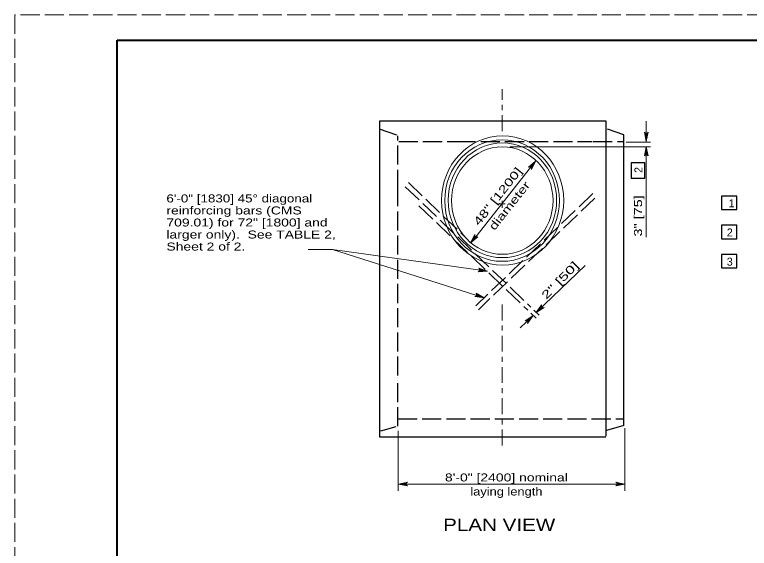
# Model space of a CAD drawing. Extents: x 1170.6 to 1204.6, y 975 to 1019.
# Drawn here: x 1170.59 to 1184.91, y 1008.62 to 1019.03 of the extents above; entities that cross this region are included whole.
import ezdxf
from ezdxf.enums import TextEntityAlignment as Align

# ---------------------------------------------------------------- set-up
doc = ezdxf.new("R2010")
doc.units = 0
doc.header["$LTSCALE"] = 0.062
doc.linetypes.add('DOT_DASHED', pattern=[7.7, 5, -1.2, 0.3, -1.2])
doc.linetypes.add('LONG_DASHED', pattern=[7.5, 6, -1.5])
doc.layers.add('1', color=7, linetype='Continuous', lineweight=13)

msp = doc.modelspace()

# ---------------------------------------------------------------- linework, layer by layer
at = {"layer": '1', "lineweight": 25}
for p, q in [((1172.59275, 1018.52625), (1204.09275, 1018.52625)), ((1177.70983, 1011.85525), (1177.70983, 1016.95867)), ((1177.70983, 1016.95867), (1178.63542, 1016.95867)), ((1178.61925, 1016.95867), (1181.86783, 1016.95867)), ((1182.46725, 1016.683), (1182.1455, 1016.79658)), ((1182.46725, 1011.89892), (1182.46725, 1016.683)), ((1177.70983, 1011.22067), (1177.70983, 1011.94267)), ((1182.11483, 1011.94267), (1182.11483, 1010.805)), ((1182.46725, 1011.01492), (1182.46725, 1011.94267)), ((1182.46725, 1011.01492), (1182.13008, 1010.9175)), ((1182.11483, 1010.78767), (1178.61925, 1010.78767))]:
    msp.add_line(p, q, dxfattribs=at)
at = {"layer": '1', "linetype": 'DOT_DASHED'}
for p, q in [((1180.09242, 1016.757), (1180.09242, 1017.57567)), ((1180.09242, 1010.625), (1180.09242, 1013.40383))]:
    msp.add_line(p, q, dxfattribs=at)
at = {"layer": '1'}
for p, q in [((1182.90225, 1016.5835), (1182.90225, 1016.95042)), ((1182.87983, 1016.71542), (1182.90225, 1016.55517)), ((1182.89092, 1016.71), (1182.90225, 1016.55517)), ((1182.92708, 1016.71733), (1182.90225, 1016.55517)), ((1182.91667, 1016.71117), (1182.90225, 1016.55517)), ((1182.90225, 1016.70833), (1182.90225, 1016.55517)), ((1182.51167, 1016.54175), (1182.98308, 1016.54175)), ((1180.24642, 1016.44842), (1182.98308, 1016.44842)), ((1182.8775, 1016.287), (1182.90225, 1016.44917)), ((1182.88783, 1016.29317), (1182.90225, 1016.44917)), ((1182.90225, 1016.296), (1182.90225, 1016.44917)), ((1182.91358, 1016.29433), (1182.90225, 1016.44917)), ((1182.92467, 1016.28892), (1182.90225, 1016.44917)), ((1182.90225, 1014.68608), (1182.90225, 1016.41675)), ((1179.48092, 1014.57158), (1180.74692, 1016.16892)), ((1180.62675, 1016.05725), (1180.74692, 1016.16892)), ((1180.63867, 1016.05558), (1180.74692, 1016.16892)), ((1180.65175, 1016.04883), (1180.74692, 1016.16892)), ((1180.65958, 1016.0405), (1180.74692, 1016.16892)), ((1180.66492, 1016.02942), (1180.74692, 1016.16892)), ((1180.01975, 1015.33858), (1180.15033, 1015.33858)), ((1180.09242, 1015.26225), (1180.09242, 1015.39567)), ((1179.56142, 1014.71717), (1179.47942, 1014.57767)), ((1179.56675, 1014.706), (1179.47942, 1014.57767)), ((1179.57458, 1014.69767), (1179.47942, 1014.57767)), ((1179.58758, 1014.69092), (1179.47942, 1014.57767)), ((1179.59958, 1014.68933), (1179.47942, 1014.57767)), ((1179.8075, 1014.02108), (1176.78533, 1014.44533)), ((1179.64575, 1014.02083), (1179.8075, 1014.02108)), ((1179.65033, 1014.06792), (1179.8075, 1014.02108)), ((1179.65258, 1014.03108), (1179.8075, 1014.02108)), ((1179.655, 1014.05675), (1179.8075, 1014.02108)), ((1179.65583, 1014.04208), (1179.8075, 1014.02108)), ((1181.71358, 1014.13283), (1180.758, 1013.21675)), ((1179.58175, 1013.537), (1179.74067, 1013.50692)), ((1179.59042, 1013.54575), (1179.74067, 1013.50692)), ((1179.59508, 1013.58233), (1179.74067, 1013.50692)), ((1179.59558, 1013.556), (1179.74067, 1013.50692)), ((1179.5975, 1013.5705), (1179.74067, 1013.50692)), ((1180.85817, 1013.34383), (1180.758, 1013.21675)), ((1180.86192, 1013.33208), (1180.758, 1013.21675)), ((1180.8685, 1013.32275), (1180.758, 1013.21675)), ((1180.88058, 1013.31433), (1180.758, 1013.21675)), ((1180.89217, 1013.31108), (1180.758, 1013.21675)), ((1180.6525, 1013.20558), (1180.75683, 1013.1055)), ((1180.70917, 1013.26567), (1180.81358, 1013.1655)), ((1180.69233, 1013.15392), (1180.44492, 1012.91667)), ((1180.55817, 1013.05958), (1180.69233, 1013.15392)), ((1180.56975, 1013.05633), (1180.69233, 1013.15392)), ((1180.58175, 1013.04792), (1180.69233, 1013.15392)), ((1180.58842, 1013.03858), (1180.69233, 1013.15392)), ((1180.59217, 1013.02683), (1180.69233, 1013.15392)), ((1178.06967, 1009.74008), (1178.06967, 1010.91117)), ((1182.48658, 1009.74008), (1182.48658, 1010.96517)), ((1178.23233, 1009.89492), (1178.07208, 1009.8725)), ((1178.22683, 1009.88383), (1178.07208, 1009.8725)), ((1178.07208, 1009.8725), (1178.656, 1009.8725)), ((1178.22525, 1009.8725), (1178.07208, 1009.8725)), ((1178.22808, 1009.85808), (1178.07208, 1009.8725)), ((1178.23417, 1009.84775), (1178.07208, 1009.8725)), ((1178.61925, 1009.8725), (1181.90908, 1009.8725)), ((1181.86783, 1009.8725), (1182.48658, 1009.8725)), ((1182.3245, 1009.84775), (1182.48658, 1009.8725)), ((1182.32633, 1009.89492), (1182.48658, 1009.8725)), ((1182.33058, 1009.85808), (1182.48658, 1009.8725)), ((1182.33175, 1009.88383), (1182.48658, 1009.8725)), ((1182.33342, 1009.8725), (1182.48658, 1009.8725))]:
    msp.add_line(p, q, dxfattribs=at)
at = {"layer": '1', "linetype": 'LONG_DASHED', "lineweight": 25}
for p, q in [((1178.03942, 1016.67467), (1177.70317, 1016.79342)), ((1178.0775, 1016.55292), (1179.20392, 1016.55292)), ((1179.20392, 1016.55292), (1181.84717, 1016.55292)), ((1181.86783, 1016.55292), (1182.46725, 1016.55292)), ((1178.06242, 1010.99833), (1178.06242, 1011.94267)), ((1178.06242, 1011.14467), (1182.46725, 1011.14467)), ((1178.02075, 1010.98642), (1177.72525, 1010.90108))]:
    msp.add_line(p, q, dxfattribs=at)
at = {"layer": '1', "linetype": 'LONG_DASHED'}
for p, q in [((1178.26517, 1015.75183), (1179.43417, 1014.631)), ((1178.20483, 1015.67117), (1180.65567, 1013.32133)), ((1181.86033, 1015.53633), (1179.5775, 1013.34775)), ((1181.90025, 1015.44875), (1179.62967, 1013.27175)), ((1178.471, 1015.297), (1180.59308, 1013.2625))]:
    msp.add_line(p, q, dxfattribs=at)
msp.add_lwpolyline([(1170.59275, 997.02625), (1204.59275, 997.02625), (1204.59275, 1019.02625), (1170.59275, 1019.02625)], close=True, dxfattribs=at)
at = {"layer": '1', "lineweight": 25}
for points in [[(1204.09275, 997.52625), (1172.59275, 997.52625), (1172.59275, 1018.52625)], [(1181.86783, 1016.95867), (1182.11483, 1016.95867), (1182.11483, 1011.877)], [(1178.656, 1010.78767), (1177.70983, 1010.78767), (1177.70983, 1011.26508)]]:
    msp.add_lwpolyline(points, dxfattribs=at)
at = {"layer": '1', "lineweight": 40}
msp.add_lwpolyline([(1172.59275, 1018.52625), (1204.09275, 1018.52625), (1204.09275, 997.52625), (1172.59275, 997.52625)], close=True, dxfattribs=at)
at = {"layer": '1', "linetype": 'LONG_DASHED', "lineweight": 25}
msp.add_lwpolyline([(1178.06242, 1011.9865), (1178.06242, 1015.62925), (1178.06242, 1016.66658)], dxfattribs=at)
at = {"layer": '1'}
for points in [[(1182.93767, 1016.73217), (1182.90225, 1016.55517), (1182.86683, 1016.73217)], [(1182.86683, 1016.27217), (1182.90225, 1016.44917), (1182.93767, 1016.27217)], [(1180.60917, 1016.05217), (1180.74692, 1016.16892), (1180.66467, 1016.00817)], [(1179.61708, 1014.69433), (1179.47942, 1014.57767), (1179.56167, 1014.73833)], [(1179.74067, 1013.50692), (1176.78533, 1014.44533), (1176.31217, 1014.44533)], [(1179.63708, 1014.08042), (1179.8075, 1014.02108), (1179.62733, 1014.01033)], [(1179.58433, 1013.59717), (1179.74067, 1013.50692), (1179.56167, 1013.53008)], [(1180.91025, 1013.31367), (1180.758, 1013.21675), (1180.86125, 1013.36483)], [(1180.54008, 1013.057), (1180.69233, 1013.15392), (1180.58908, 1013.00583)], [(1178.24908, 1009.83708), (1178.07208, 1009.8725), (1178.24908, 1009.90792)], [(1182.30958, 1009.83708), (1182.48658, 1009.8725), (1182.30958, 1009.90792)]]:
    msp.add_lwpolyline(points, dxfattribs=at)
at = {"layer": '1', "lineweight": 25}
for points in [[(1182.61, 1015.8375), (1182.87175, 1015.8375), (1182.87175, 1016.13617), (1182.61, 1016.13617)], [(1184.36975, 1015.48867), (1184.36975, 1015.22717), (1184.66833, 1015.22717), (1184.66833, 1015.48867)], [(1184.36975, 1014.91917), (1184.36975, 1014.65742), (1184.66833, 1014.65742), (1184.66833, 1014.91917)], [(1184.36975, 1014.34942), (1184.36975, 1014.08767), (1184.66833, 1014.08767), (1184.66833, 1014.34942)]]:
    msp.add_lwpolyline(points, close=True, dxfattribs=at)
at = {"layer": '1'}
for centre, start, end in [((1182.90223, 1016.74647), 202.08782, 337.91395), ((1182.90231, 1016.25786), 22.08782, 157.91395), ((1180.62809, 1016.01895), 343.68884, 119.51496), ((1179.59823, 1014.72758), 163.68884, 299.51496), ((1179.61804, 1014.04731), 284.18551, 60.01164), ((1179.55947, 1013.56813), 273.41452, 49.24065), ((1180.89604, 1013.34917), 155.87766, 291.70378), ((1180.55428, 1013.02149), 335.87164, 111.69776), ((1178.26335, 1009.87253), 112.08782, 247.91395), ((1182.2953, 1009.87253), 292.08605, 67.91218)]:
    msp.add_arc(centre, 0.0382, start, end, dxfattribs=at)
for centre, major_axis in [((1180.10282, 1015.40421), (0, 1.2601)), ((1180.09277, 1015.40042), (0, 1.18434)), ((1180.09906, 1015.407), (0, 1.11924)), ((1180.09599, 1015.4005), (0, 1.04699))]:
    msp.add_ellipse(centre, major_axis=major_axis, ratio=0.944544, dxfattribs=at)

# ---------------------------------------------------------------- texts
for s, width, p in [('48" [1200]', 1.45, (1180.06718, 1015.4353)), ('diameter', 1.4, (1180.29725, 1015.25284))]:
    msp.add_text(s, height=0.156, rotation=51.601, dxfattribs=dict(at, width=width)).set_placement(p, align=Align.CENTER)
msp.add_text('2', height=0.156, rotation=90, dxfattribs=at).set_placement((1182.82825, 1015.93942))
for s, height, width, p in [('6\'-0" [1830] 45° diagonal', 0.156, 1.25, (1173.54975, 1015.36475)), ('reinforcing bars (CMS', 0.156, 1.3, (1173.54975, 1015.13008)), ('709.01) for 72" [1800] and', 0.156, 1.3, (1173.54975, 1014.89542)), ('larger only).  See TABLE 2,', 0.156, 1.3, (1173.54975, 1014.66075)), ('Sheet 2 of 2.', 0.156, 1.3, (1173.54975, 1014.42608)), ('PLAN VIEW', 0.24, 1.25, (1178.94367, 1008.95808))]:
    msp.add_text(s, height=height, dxfattribs=dict(at, width=width)).set_placement(p)
for s, rotation, width, p in [('3" [75]', 90, 1.35, (1182.82025, 1014.69967)), ('2" [50]', 45.652, 1.55, (1180.953, 1013.46125))]:
    msp.add_text(s, height=0.156, rotation=rotation, dxfattribs=dict(at, width=width)).set_placement(p)
for s, p in [('1', (1184.5085, 1015.26958)), ('2', (1184.47167, 1014.70092)), ('3', (1184.47167, 1014.13117))]:
    msp.add_text(s, height=0.156, dxfattribs=at).set_placement(p)
for s, width, p in [('8\'-0" [2400] nominal', 1.3, (1180.1765, 1009.923)), ('laying length', 1.2, (1180.17646, 1009.649))]:
    msp.add_text(s, height=0.156, dxfattribs=dict(at, width=width)).set_placement(p, align=Align.CENTER)

doc.saveas('drawing.dxf')
